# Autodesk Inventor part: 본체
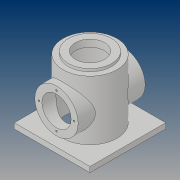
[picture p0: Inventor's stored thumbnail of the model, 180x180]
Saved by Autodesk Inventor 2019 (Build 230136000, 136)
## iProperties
Created: 2019-03
Part Number: 본체
Material: 일반
Document SubType Name: Modeling
Designer: PC312-20
Density: 1 g/cm^3
Appearance: 기본값
Author: PC312-20
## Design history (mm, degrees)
sketch "스케치1"
  geometry: L1 (0, 0)-(0, 125); L2 (-27, 125)-(-40, 125); L3 (-40, 125)-(-40, 120); L4 (-40, 120)-(-50, 120); L5 (-50, 120)-(-50, 0); L6 (-27, 125)-(-27, 112); L7 (-27, 112)-(-45, 112); L8 (-45, 112)-(-45, 0); L9 (-45, 0)-(-50, 0)
  constraints: 18 end point, 5 vertical, 4 horizontal, 1 point on line
  dimensions: "d1" = 125 distance of L1.start L1.end; "d2" = 54 diameter of L6 L1; "d3" = 80 diameter of L3 L1; "d4" = 100 diameter of L5 L1; "d5" = 13 distance between parallel lines of L7 L2; "d6" = 112 distance between parallel lines of L9 L7; "d7" = 120 distance between parallel lines of L9 L4; "d8" = 90 diameter of L8 L1
revolve "회전1" sketch "스케치1" stored, may be unused: angle "d9" = 90 deg
sketch "스케치2"
  geometry: L1 (70, 70)-(-70, 70); L2 (-70, 70)-(-70, -70); L3 (-70, -70)-(70, -70); L4 (70, -70)-(70, 70); L5 (70, 70)-(-70, -70); L6 (-70, 70)-(70, -70); 2 further points
  constraints: 12 end point, 2 midpoint, 2 parallel, 1 horizontal, 1 perpendicular
  dimensions: "d10" = 140 distance of L3.end L2.end; "d11" = 140 distance of L2.end L1.end
extrude "돌출1" join sketch "스케치2" distance "d12" = 10; taper "d13" = 0 deg
sketch "스케치3"
  geometry: C1 r 45 at (70, -70); 1 further point
  constraints: 1 centre point, 1 coincident
  dimensions: "d14" = 90 diameter of C1
extrude "돌출2" cut sketch "스케치3" distance "d15" = 10; taper "d16" = 0 deg
node "작업 평면1"
sketch "스케치4"
  geometry: L1 (-70, 0)-(70, 0) reference; C1 r 40 at (0, 60); 2 further points
  constraints: 1 centre point, 1 midpoint, 1 vertical alignment
  dimensions: "d18" = 80 diameter of C1; "d19" = 60 distance from line of L1 C1.centre
extrude "돌출3" join sketch "스케치4" stored distance "d20" = 10; taper "d21" = 0 deg
sketch "스케치5"
  geometry: C1 r 40 at (0, 0) reference; 2 further points
  constraints: 1 vertical alignment
  dimensions: "d22" = 32.5 distance of C1.centre point (0, 32.5)
hole "구멍1" sketch "스케치5" at (0, 32.5) diameter "d23" = 3.242; stored, may be unused: countersink angle "d27" = 90 deg, drill point angle "d29" = 118 deg; dims "d24" = 8, "d25" = 4, "d26" = 2, "d28" = 10
sketch "스케치6"
  geometry: C1 r 40 at (0, 0) reference; C2 r 27 at (0, 0); 1 further point
  constraints: 1 centre point, 1 coincident
  dimensions: "d33" = 54 diameter of C2
extrude "돌출4" cut sketch "스케치6" extent not by distance; stored distance "d34" = 10; taper "d35" = 0 deg
node "솔리드1"
pattern_circular "원형 패턴1" dims angle "d31" = 360 deg
mirror "미러1"
other parameters: "d17" = 62
